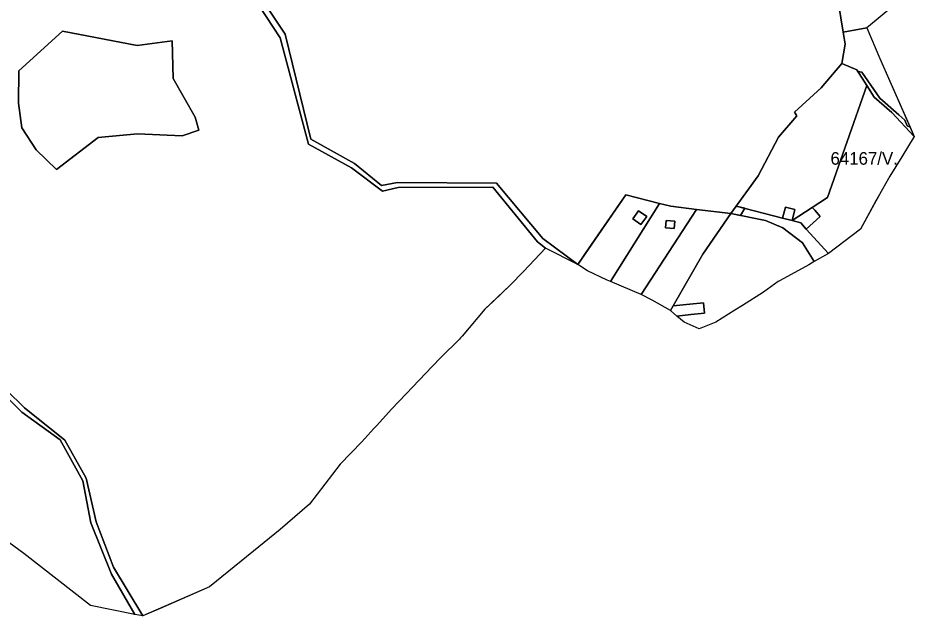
# Model space of a CAD drawing. Extents: x -502026 to -497664, y -1143484 to -1138019.
# Drawn here: x -498590 to -498018, y -1142246 to -1141865 of the extents above; entities that cross this region are included whole.
import ezdxf

# ---------------------------------------------------------------- set-up
doc = ezdxf.new("R2010")
doc.units = 0
for name, color, linetype in [('25', 7, 'Continuous'), ('31', 7, 'Continuous'), ('37', 7, 'Continuous'), ('43', 7, 'Continuous'), ('55', 7, 'Continuous'), ('62', 7, 'Continuous')]:
    doc.layers.add(name, color=color, linetype=linetype)

msp = doc.modelspace()

# ---------------------------------------------------------------- linework, layer by layer
at = {"layer": '25'}
for points in [[(-498181.97, -1141983.31), (-498213.28, -1142032.92), (-498215.27, -1142032.07), (-498227.75, -1142026.26), (-498234.08, -1142022.26), (-498203.54, -1141977.96)], [(-498158.51, -1141987.12), (-498193.73, -1142041.27), (-498213.28, -1142032.92), (-498181.97, -1141983.31), (-498174.77, -1141985.1)], [(-498190.03, -1141991.71), (-498195.42, -1141987.98), (-498199, -1141993.04), (-498193.85, -1141996.82)], [(-498136.77, -1141989.83), (-498154.54, -1142015.64), (-498173.48, -1142048.49), (-498175.1, -1142051.3), (-498186.76, -1142044.81), (-498193.73, -1142041.27), (-498158.51, -1141987.12)], [(-498172.43, -1141994.61), (-498177.91, -1141994.19), (-498178.27, -1141998.93), (-498172.8, -1141999.34)]]:
    msp.add_lwpolyline(points, close=True, dxfattribs=at)
at = {"layer": '31'}
for points in [[(-498050.26, -1141908.4), (-498075.22, -1141979.52), (-498084.97, -1141985.9), (-498097.79, -1141994.3), (-498095.95, -1141987.26), (-498102.05, -1141985.66), (-498103.9, -1141992.7), (-498133.27, -1141985.01), (-498119.3, -1141965.77), (-498106.32, -1141941.15), (-498094.73, -1141927.58), (-498096.19, -1141925.35), (-498079.32, -1141909.8), (-498066.06, -1141894.38), (-498056.61, -1141898.34)], [(-498020.05, -1141940.73), (-498028.02, -1141953.67), (-498035.62, -1141966), (-498043.1, -1141979.13), (-498054.34, -1141999.77), (-498074.7, -1142015.26), (-498088.76, -1141999.66), (-498079.83, -1141991.61), (-498083.35, -1141987.7), (-498084.97, -1141985.9), (-498075.22, -1141979.52), (-498050.26, -1141908.4), (-498045.57, -1141915.83), (-498034.33, -1141925.63)], [(-498083.69, -1142020.28), (-498087.13, -1142022.28), (-498093.66, -1142026.07), (-498105.77, -1142032.5), (-498106.66, -1142032.97), (-498115.99, -1142039.66), (-498129.33, -1142048.17), (-498134.17, -1142051.25), (-498146.32, -1142058.91), (-498156.92, -1142063.12), (-498166.49, -1142058.88), (-498170.99, -1142054.92), (-498162.13, -1142053.97), (-498153.47, -1142053.04), (-498154.18, -1142046.42), (-498162.84, -1142047.35), (-498173.48, -1142048.49), (-498154.54, -1142015.64), (-498136.77, -1141989.83), (-498114.62, -1141994.26), (-498103.61, -1141998.82), (-498091.15, -1142008.43)]]:
    msp.add_lwpolyline(points, close=True, dxfattribs=at)
at = {"layer": '37'}
msp.add_lwpolyline([(-498017.71, -1141846.21), (-498022.83, -1141849.82), (-498027.83, -1141853.34), (-498029.01, -1141854.28), (-498034.07, -1141858.33), (-498044.28, -1141866.85), (-498050.16, -1141871.76), (-498065.32, -1141874.58), (-498075.32, -1141812.96), (-498074.98, -1141784.5), (-498057.54, -1141775.53), (-498056.02, -1141780.8), (-498035.83, -1141821.06)], close=True, dxfattribs=at)
at = {"layer": '43'}
for points in [[(-498075.32, -1141812.96), (-498065.32, -1141874.58), (-498064.11, -1141882.22), (-498066.06, -1141894.38), (-498079.32, -1141909.8), (-498096.19, -1141925.35), (-498094.73, -1141927.58), (-498106.32, -1141941.15), (-498119.3, -1141965.77), (-498133.27, -1141985.01), (-498136.77, -1141989.83), (-498158.51, -1141987.12), (-498174.77, -1141985.1), (-498181.97, -1141983.31), (-498203.54, -1141977.96), (-498234.08, -1142022.26), (-498256.16, -1142005.55), (-498285.68, -1141970.55), (-498348.77, -1141970.04), (-498358.83, -1141971.96), (-498375.96, -1141957.95), (-498403.77, -1141942.42), (-498420.03, -1141875.81), (-498444.04, -1141839.62)], [(-498436.54, -1141857.84), (-498423.37, -1141878.17), (-498405.21, -1141945.59), (-498377.9, -1141960.78), (-498358.19, -1141975.54), (-498348.22, -1141973.24), (-498288.05, -1141973.01), (-498259.65, -1142007.67), (-498254.59, -1142011.76), (-498268.59, -1142026.68), (-498277.04, -1142035.34), (-498293.03, -1142050.64), (-498307.58, -1142067.62), (-498308.63, -1142068.84), (-498309.32, -1142069.53), (-498321.09, -1142081.18), (-498326.66, -1142086.99), (-498343.08, -1142104.34), (-498352.42, -1142114.18), (-498361.88, -1142124.42), (-498363.65, -1142126.34), (-498371.26, -1142134.89), (-498385.04, -1142149.14), (-498404.52, -1142174.39), (-498423.37, -1142190.64), (-498440.23, -1142204.31), (-498468.14, -1142227.12), (-498510.61, -1142245.56), (-498529.31, -1142214.45), (-498540.33, -1142185.7), (-498546.52, -1142157.94), (-498560.15, -1142133.78), (-498585.79, -1142113.33), (-498609.2, -1142090.53)], [(-498611.31, -1142092.76), (-498587.53, -1142115.93), (-498563.25, -1142133.53), (-498548.75, -1142159.68), (-498543.55, -1142186.32), (-498530.42, -1142218.91), (-498515.69, -1142244.53), (-498543.84, -1142238.79), (-498586.16, -1142205.84), (-498617.46, -1142183.22)]]:
    msp.add_lwpolyline(points, dxfattribs=at)
for points in [[(-498020.05, -1141940.73), (-498034.33, -1141925.63), (-498045.57, -1141915.83), (-498050.26, -1141908.4), (-498056.61, -1141898.34), (-498066.06, -1141894.38), (-498064.11, -1141882.22), (-498065.32, -1141874.58), (-498050.16, -1141871.76), (-498041.9, -1141891.28)], [(-498561.64, -1141873.83), (-498514.3, -1141882.99), (-498492.04, -1141880.02), (-498491.39, -1141903.91), (-498477.33, -1141928.57), (-498475.08, -1141936.77), (-498485.61, -1141940.31), (-498514.06, -1141939.18), (-498539.05, -1141941.51), (-498565.42, -1141961.69), (-498578.44, -1141949.25), (-498587.44, -1141935.26), (-498589.61, -1141919.58), (-498589.45, -1141898.99)], [(-498561.64, -1141873.83), (-498589.45, -1141898.99), (-498589.61, -1141919.58), (-498587.44, -1141935.26), (-498578.44, -1141949.25), (-498565.42, -1141961.69), (-498539.05, -1141941.51), (-498514.06, -1141939.18), (-498485.61, -1141940.31), (-498475.08, -1141936.77), (-498477.33, -1141928.57), (-498491.39, -1141903.91), (-498492.04, -1141880.02), (-498514.3, -1141882.99)], [(-498510.61, -1142245.56), (-498515.69, -1142244.53), (-498530.42, -1142218.91), (-498543.55, -1142186.32), (-498548.75, -1142159.68), (-498563.25, -1142133.53), (-498587.53, -1142115.93), (-498611.31, -1142092.76), (-498616.14, -1142075.16), (-498609.08, -1142042.07), (-498621.71, -1141994.61), (-498622.04, -1141942.16), (-498619.17, -1141940.28), (-498618.74, -1141993.74), (-498606.48, -1142042.32), (-498613.54, -1142075.78), (-498609.2, -1142090.53), (-498585.79, -1142113.33), (-498560.15, -1142133.78), (-498546.52, -1142157.94), (-498540.33, -1142185.7), (-498529.31, -1142214.45)]]:
    msp.add_lwpolyline(points, close=True, dxfattribs=at)
at = {"layer": '55'}
msp.add_lwpolyline([(-498444.04, -1141839.62), (-498420.03, -1141875.81), (-498403.77, -1141942.42), (-498375.96, -1141957.95), (-498358.83, -1141971.96), (-498348.77, -1141970.04), (-498285.68, -1141970.55), (-498256.16, -1142005.55), (-498234.08, -1142022.26), (-498254.59, -1142011.76), (-498259.65, -1142007.67), (-498288.05, -1141973.01), (-498348.22, -1141973.24), (-498358.19, -1141975.54), (-498377.9, -1141960.78), (-498405.21, -1141945.59), (-498423.37, -1141878.17), (-498436.54, -1141857.84)], dxfattribs=at)
for points in [[(-498103.9, -1141992.7), (-498097.79, -1141994.3), (-498092.28, -1141995.76), (-498088.76, -1141999.66), (-498074.7, -1142015.26), (-498083.69, -1142020.28), (-498091.15, -1142008.43), (-498103.61, -1141998.82), (-498114.62, -1141994.26), (-498136.77, -1141989.83), (-498133.27, -1141985.01)], [(-498097.79, -1141994.3), (-498103.9, -1141992.7), (-498102.05, -1141985.66), (-498095.95, -1141987.26)], [(-498088.76, -1141999.66), (-498092.28, -1141995.76), (-498097.79, -1141994.3), (-498084.97, -1141985.9), (-498083.35, -1141987.7), (-498079.83, -1141991.61)], [(-498190.03, -1141991.71), (-498193.85, -1141996.82), (-498199, -1141993.04), (-498195.42, -1141987.98)], [(-498172.43, -1141994.61), (-498172.8, -1141999.34), (-498178.27, -1141998.93), (-498177.91, -1141994.19)], [(-498170.99, -1142054.92), (-498175.1, -1142051.3), (-498173.48, -1142048.49), (-498162.84, -1142047.35), (-498154.18, -1142046.42), (-498153.47, -1142053.04), (-498162.13, -1142053.97)]]:
    msp.add_lwpolyline(points, close=True, dxfattribs=at)
at = {"layer": '62'}
for points in [[(-498038.02, -1141816.67), (-498037.99, -1141816.74), (-498035, -1141824), (-498018.52, -1141846.78), (-498022.83, -1141849.82), (-498027.83, -1141853.34), (-498029.01, -1141854.28), (-498034.07, -1141858.33), (-498044.28, -1141866.85), (-498050.16, -1141871.76), (-498065.32, -1141874.58), (-498075.32, -1141812.96), (-498074.98, -1141784.5), (-498057.54, -1141775.53), (-498056.02, -1141780.8)], [(-498022.61, -1141934.95), (-498020.05, -1141940.73), (-498028.02, -1141953.67), (-498035.62, -1141966), (-498043.1, -1141979.13), (-498044.46, -1141981.63), (-498054.34, -1141999.77), (-498074.7, -1142015.26), (-498083.69, -1142020.28), (-498087.13, -1142022.28), (-498093.66, -1142026.07), (-498105.77, -1142032.5), (-498106.66, -1142032.97), (-498115.99, -1142039.66), (-498129.33, -1142048.17), (-498134.17, -1142051.25), (-498146.32, -1142058.91), (-498156.92, -1142063.12), (-498166.49, -1142058.88), (-498170.99, -1142054.92), (-498175.1, -1142051.3), (-498186.76, -1142044.81), (-498193.73, -1142041.27), (-498213.28, -1142032.92), (-498215.27, -1142032.07), (-498227.75, -1142026.26), (-498234.08, -1142022.26), (-498229.98, -1142016.31), (-498229.09, -1142015.02), (-498203.54, -1141977.96), (-498181.97, -1141983.31), (-498174.77, -1141985.1), (-498158.51, -1141987.12), (-498136.77, -1141989.83), (-498130.49, -1141991.08), (-498127.89, -1141986.42), (-498133.27, -1141985.01), (-498119.3, -1141965.77), (-498106.32, -1141941.15), (-498094.73, -1141927.58), (-498096.19, -1141925.35), (-498079.32, -1141909.8), (-498066.06, -1141894.38), (-498056.61, -1141898.34), (-498055.91, -1141899.45), (-498053.5, -1141900), (-498042, -1141916.5), (-498030, -1141927), (-498026, -1141930.5), (-498024.5, -1141934)]]:
    msp.add_lwpolyline(points, close=True, dxfattribs=at)
msp.add_lwpolyline([(-498075.32, -1141812.96), (-498065.32, -1141874.58), (-498050.16, -1141871.76), (-498041.9, -1141891.28), (-498022.61, -1141934.95), (-498024.5, -1141934), (-498026, -1141930.5), (-498030, -1141927), (-498042, -1141916.5), (-498053.5, -1141900), (-498055.91, -1141899.45), (-498056.61, -1141898.34), (-498066.06, -1141894.38), (-498079.32, -1141909.8), (-498096.19, -1141925.35), (-498094.73, -1141927.58), (-498106.32, -1141941.15), (-498119.3, -1141965.77), (-498133.27, -1141985.01), (-498127.89, -1141986.42), (-498130.49, -1141991.08), (-498136.77, -1141989.83), (-498158.51, -1141987.12), (-498174.77, -1141985.1), (-498181.97, -1141983.31), (-498203.54, -1141977.96), (-498229.09, -1142015.02), (-498229.98, -1142016.31), (-498234.08, -1142022.26), (-498254.59, -1142011.76), (-498268.59, -1142026.68), (-498277.04, -1142035.34), (-498287.89, -1142045.72), (-498293.03, -1142050.64), (-498307.58, -1142067.62), (-498308.63, -1142068.84), (-498309.32, -1142069.53), (-498321.09, -1142081.18), (-498326.66, -1142086.99), (-498343.08, -1142104.34), (-498352.42, -1142114.18), (-498361.88, -1142124.42), (-498363.65, -1142126.34), (-498371.26, -1142134.89), (-498385.04, -1142149.14), (-498404.52, -1142174.39), (-498423.37, -1142190.64), (-498440.23, -1142204.31), (-498468.14, -1142227.12), (-498499.6, -1142240.78), (-498510.61, -1142245.56), (-498515.69, -1142244.53), (-498543.84, -1142238.79), (-498586.16, -1142205.84), (-498617.46, -1142183.22)], dxfattribs=at)

# ---------------------------------------------------------------- texts
msp.add_text('64167/V.', height=8, dxfattribs=at).set_placement((-498073.34, -1141958.74))

doc.saveas('drawing.dxf')
